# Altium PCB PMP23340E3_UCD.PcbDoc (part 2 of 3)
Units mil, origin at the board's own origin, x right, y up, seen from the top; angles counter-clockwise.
Board outline 2299.21 x 1157.48 mil, 14 copper layers (Top Layer, Layer 1, Layer 2, Layer 3, Layer 4, Layer 5, Layer 6, Layer 7, Layer 8, Layer 9, Layer 10, Layer 11, Layer 12, Bottom Layer), stack 130 mil thick; 242 components, 71 nets, 1021 pads, 321 vias.
Unrouted connection lines stored in the file: 1.
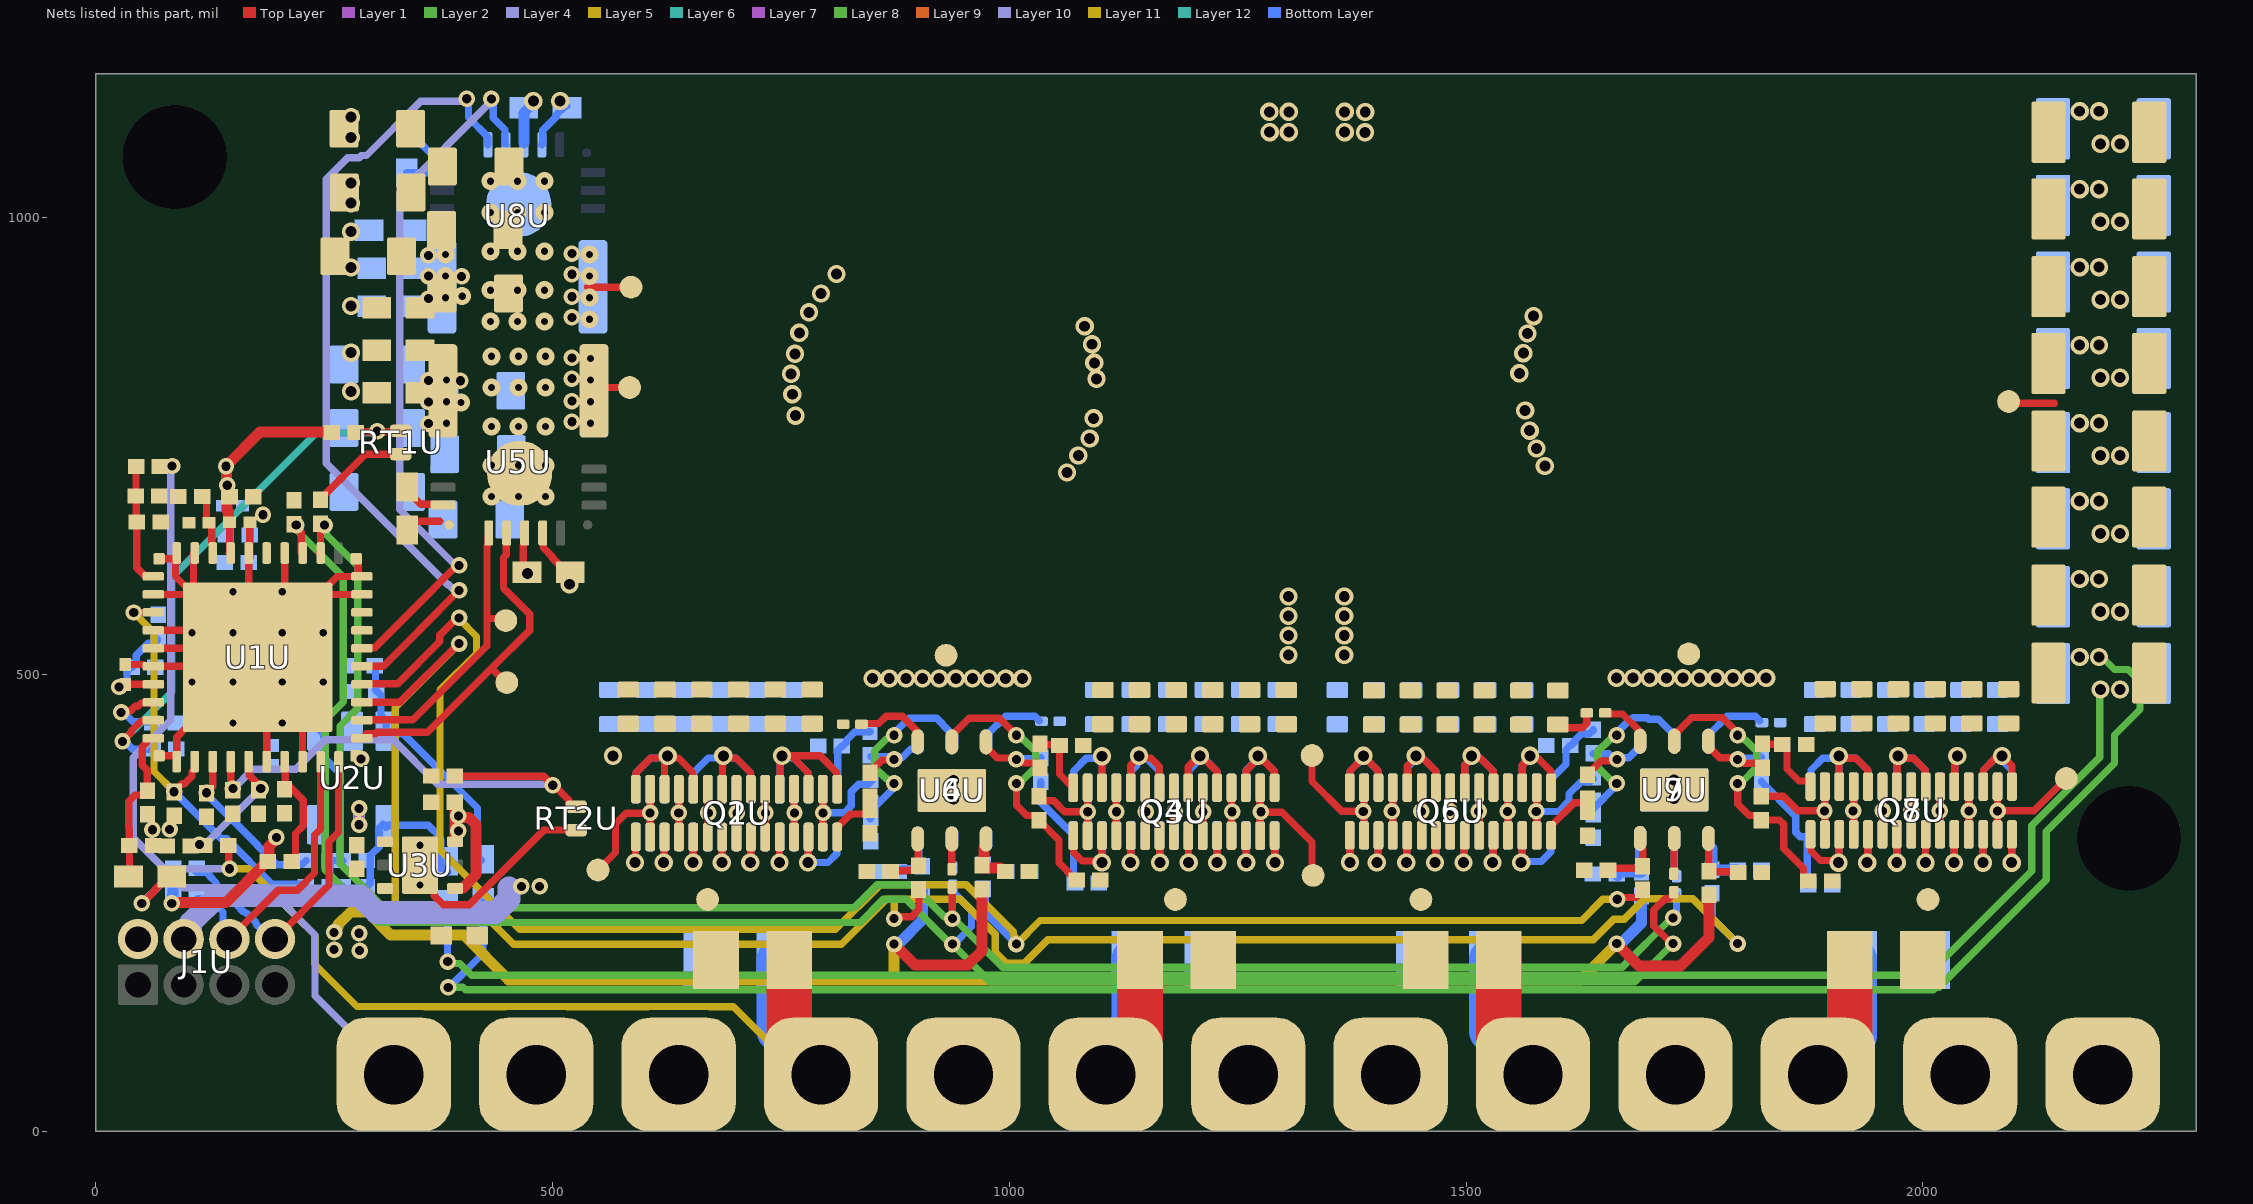
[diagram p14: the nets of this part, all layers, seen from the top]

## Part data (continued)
U2U: library part CMP-0032028-2, "CMOS Amplifier 1 Circuit Rail-to-Rail SOT-23-5", Digikey Part Number=296-TLV365DBVRCT-ND, Input Bias Current=0.000005uA, Input Offset Voltage=0.4mV, Manufacturer="Texas Instruments", Max Supply Voltage=5.5V, Min Supply Voltage=2.2V, Mouser Part Number=595-TLV365DBVR, Nominal Supply Current=4.6mA, Operating Temperature Range="-40°C to +125°C", Output Current Per Channel=85mA, Voltage Gain=120dB
U3U: library part CMP-0013427-7, "500mA LDO, DRV0006A (WSON-6)", Alternate Manufacturer="Texas Instruments"
U4U U6U U7U U9U: library part CMP-0013422-3, "UCD7xxx Low Side Power MOSFET Driver with Body Diode Conduction Sensing, DRS0006A (WSON-6)", Alternate Manufacturer="Texas Instruments"
U5U U8U: library part CMP-0097820-2, Manufacturer="Texas Instruments", Operating Temperature Range=to
ZZ1U: library part CMP-0003616-3
ZZ2U: library part CMP-0077236-1
ZZ3U: library part CMP-0077237-1
ZZ4U: library part CMP-0077238-1

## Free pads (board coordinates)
  round 114.17 hole 114.17 unplated: 2(86.41,1066.47) 2(2225.59,320.81)

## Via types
v1: diameter 20, hole 12, Top Layer to Bottom Layer, tented both sides, 153 vias
v2: diameter 18, hole 10, Top Layer to Bottom Layer, tented both sides, 108 vias
v3: diameter 19.68, hole 7.87, Top Layer to Bottom Layer, tented both sides, 58 vias
v4: diameter 19.68, hole 7.87, Top Layer to Bottom Layer, 2 vias

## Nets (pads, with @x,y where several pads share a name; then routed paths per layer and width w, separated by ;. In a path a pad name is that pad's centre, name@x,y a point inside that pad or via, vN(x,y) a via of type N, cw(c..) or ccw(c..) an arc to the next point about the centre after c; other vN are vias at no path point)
3_3V_A: C1U.2 C2U.1 R1U.1 U1U.37 | length 100.7
  Top Layer w8: C2U.1@30.58,489.81 C2U.1@31.76,490.99 ; C2U.1@31.93,489.14 U1U.37@61.73,489.14
  Bottom Layer w8: v2@29.38,489.73 34.16,494.51 34.16,503.61 38.43,507.88 C1U.2@39.22,507.88 39.88,507.88 44.15,512.14 44.15,521.11 57.46,534.42 64.08,534.42 67.13,537.47 R1U.1@67.13,538.64
  other v2: 25.59,486.22
3_3V_D: C3U.2 C4U.2 C5U.2 C6U.1 C7U.1 C17U.1 C25U.1 R1U.2 R2U.2 R3U.1 R4U.1 R9U.2 R10U.2 U1U.27 U2U.5 U3U.1 | length 641.3
  Top Layer w8: U1U.27@145.89,632.89 146.54,633.53 C6U.1@146.54,666.32
  Top Layer w12: v2@83.32,250.28 142.78,250.28 185.32,292.81 185.89,292.81 R2U.2@188.53,295.46 ; v2(143.86,707.01) 143.86,679.32 145.25,677.94 C6U.1@145.25,669.65 ; v2@145.51,706.02 143.19,708.34 143.19,727.2 v2(142.52,727.87) 179.88,765.24 258.18,765.24 R9U.2@259.96,763.46 ; R2U.2@189.65,295.46 189.65,311.93 197.67,319.94 v2(197.67,321.56) ; v2@288.7,354.31 v2@290.43,352.58
  Layer 1 w12: v2@287.23,333.89 288.33,334.99 v2(288.33,335.48) v2(288.33,353.31)
  Layer 2 w12: v2@288.33,334.82 v2(288.33,335.48) v2(288.33,353.31)
  Layer 4 w12: v2@288.12,335.32 v2(288.33,335.48) v2(288.33,353.31)
  Layer 5 w12: v2(288.33,353.31) 288.33,335.64 v2@288.47,335.5
  Layer 6 w12: v2(288.33,353.31) 288.33,337.95 v2@289.72,336.56
  Layer 7 w12: v2@288.12,336.56 288.33,336.77 v2(288.33,353.31)
  Layer 8 w12: v2@287.58,336.38 288.33,337.13 v2(288.33,353.31)
  Layer 9 w12: v2@287.41,336.03 288.33,336.95 v2(288.33,353.31)
  Layer 10 w12: v2@287.94,334.61 288.33,334.99 v2(288.33,335.48) v2(288.33,353.31)
  Layer 11 w12: v2@288.33,335.71 v2(288.33,353.31)
  Layer 12 w12: v2@287.05,334.61 v2@288.33,335.88 ; v2@287.23,334.43 v2(288.33,335.48) v2@288.33,335.88 ; v2(288.33,353.31) v2@288.33,335.88
  Bottom Layer w12: v2@83.32,250.28 83.98,250.94 83.98,258.24 R3U.1@84.65,258.91 84.65,285.61 R4U.1@85.56,285.61 ; v2(288.33,353.31) v2(288.33,335.48) 288.33,335.19 v2@289.13,334.38
  other v2: 83.14,249.4
5V: C24U.1 C44U.2 C94U.2 J1U.2 L1U.1 L2U.1 L3U.1 L4U.1 U3U.4 U3U.6 U5U.14 U8U.14 | length 2261.3
  Top Layer w8: U5U.14@468.61,657.45 468.61,642.01 467.81,641.21 467.81,615.21 v1(472.77,610.25)
  Top Layer w12: C24U.1@392.99,360.1 393.21,359.88 393.21,344.89 v2@393.44,344.66 ; v2@393.06,325.22 393.06,316.99 393.16,316.9 U3U.6@393.21,316.9 ; U3U.6@393.28,316.9 U3U.6@393.21,316.9 ; U3U.4@396.14,265.81 398.65,265.81 399.22,266.39 401.78,266.39 416.14,280.74 416.14,335.7 408.33,343.52 394.58,343.52 v2@393.44,344.66 ; v2(873.92,204.75) 896.77,181.9 899.17,181.9 ; 899.17,181.75 954.97,181.75 ; 954.97,182.3 970.05,197.38 L2U.1@970.05,265.17 ; v2(1664.88,205.38) 1689.35,180.91 1734.6,180.91 1765.81,212.12 L4U.1@1765.81,258.78 1765.81,259.15 L4U.1@1764.48,260.49 ; U3U.6@393.21,316.9 393.12,316.99 393.12,328.11 392.95,328.28 393.19,328.52 393.19,344.42 v2@393.44,344.66
  Layer 1 w12: J1U.2@46.09,206.08 J1U.2@46.09,211.13
  Layer 11 w12: v2(260.93,217.57) 260.93,219.2 265.18,223.44 265.18,226.21 278.65,239.68 297.71,239.68 322.8,214.59 402.95,214.59 451.79,165.75 1619.05,165.75 ; 872.73,166.53 873.92,167.72 v2(873.92,204.75) ; 1619.05,165.67 1625.18,165.67 v2(1664.88,205.38)
  Bottom Layer w12: U8U.14@468.5,1081.69 468.5,1114.8 479.51,1125.8 C94U.2@479.51,1126.45 ; v2(873.92,204.75) 875.07,205.89 879.57,205.89 904.71,231.03 L1U.1@904.71,263.99 904.71,265 L1U.1@905.56,265.85 ; v2(1664.88,205.38) 1666.03,206.52 1670.53,206.52 1691.8,227.79 1691.8,257.17 L3U.1@1690.96,258
  other v1: 479,1127.46
  other v2: 260.93,198.84 396.86,328.77 396.86,345.15
ADDR0: C13U.1 U1U.38 | length 74.3
  Top Layer w8: v2@29.23,459.03 30.55,460.35 38.25,460.35 42.98,465.08 45.87,465.08 49.56,468.76 61.05,468.76 U1U.38@61.73,469.45
  Bottom Layer w8: v2@29.02,458.25 30.65,458.25 40.74,448.16 60.54,448.16 C13U.1@61.79,446.91
  other v2: 27.76,458.44
AGND: C1U.1 C2U.2 C3U.1 C4U.1 C5U.1 C6U.2 C7U.2 C8U.1 C9U.2 C10U.1 C11U.2 C12U.2 C13U.2 C14U.1 C15U.1 C17U.2 C18U.1 C19U.1 C20U.1 C21U.1 C22U.1 C23U.1 C24U.2 C25U.2 NT1U.2 R14U.1 R15U.1 R16U.1 R17U.1 RT1U.2 RT2U.2 U1U.1 U1U.6 U1U.8 U1U.19 U1U.20 U1U.24 U1U.26 U1U.29 U1U.30 U1U.32 U1U.34 U1U.35 U1U.36 U1U.41 U1U.A1 U1U.A2 U1U.A3 U1U.A4 U2U.2 U3U.3 U3U.7@354.9,291.31 | length 1190
  Top Layer w8: C2U.2@32.22,510.82 52.25,510.82 54.25,508.82 98.22,508.82 103.93,503.11 U1U.41@103.93,492.65 ; U1U.35@61.73,528.51 98.22,528.51 105.1,535.39 U1U.41@105.1,544.48 ; U1U.34@61.73,548.19 102.56,548.19 U1U.41@104.16,546.59 ; U1U.32@61.73,587.56 U1U.41@107.01,587.56 ; U1U.A1@69.29,410.83 86.22,410.83 U1U.1@86.66,410.39 ; U1U.A4@69.29,626.57 85.14,626.57 U1U.30@85.66,626.05 ; U1U.30@87.33,626.05 87.33,607.25 U1U.41@107.01,587.56 ; U1U.1@88.58,404.53 88.58,431.34 98.25,441.01 142.81,441.01 U1U.41@149.19,447.39 ; U1U.29@107.01,632.84 107.01,593.46 U1U.41@112.37,588.1 ; U1U.41@110.96,583.41 110.96,583.61 U1U.41@107.01,587.56 ; U1U.41@125.03,585.99 123.46,587.56 U1U.41@107.01,587.56 ; U1U.41@147.55,590.68 161.61,590.68 167.32,596.39 U1U.26@167.32,632.87 ; C6U.2@168.58,666.32 168.58,627.08 U1U.26@168.63,627.03 ; U1U.6@187.01,404.53 187.01,441.01 192.22,446.22 U1U.41@202.43,446.22 ; U1U.41@206.29,589.14 206.69,589.55 U1U.24@206.69,632.87 ; U1U.41@224.84,456.13 226.38,454.59 U1U.8@226.38,404.53 ; U1U.41@235.02,586.7 235.89,587.56 U1U.19@290.08,587.56 ; U1U.41@240.89,589.04 246.28,589.04 264.49,607.25 U1U.20@290.08,607.25 ; C11U.2@243.39,692.81 246.94,692.81 295.23,741.09 RT1U.2@333.68,741.09 ; U1U.A3@283.97,627.04 284.58,627.04 U1U.A3@285.04,626.57 287.34,624.28 287.34,608.01 288.06,607.28 U1U.20@291.34,607.28 ; U3U.7@353.56,270.38 364.02,270.38 370.58,263.81 370.58,257.82 380.6,247.81 408.66,247.81 490.45,329.59 RT2U.2@525.89,329.59
  other v2: 288.77,197.66 288.18,216.68 61.94,329.92 80.81,330.34 290.35,407.48 183.07,674.8
  other v3: 150.2,446.85 204.13,446.85 105.32,491.73 150.2,491.73 204.13,491.73 249.02,491.73 105.32,545.67 150.2,545.67 204.13,545.67 249.02,545.67 150.2,590.55 204.13,590.55
  other v4: 354.9,269.65 354.9,312.96
BP18: C8U.2 C9U.1 U1U.28 | length 65.4
  Top Layer w8: C8U.2@116.32,694.72 116.93,694.72 121.2,690.45 121.2,668.14 121.81,667.54 C9U.1@123.58,667.54 ; C9U.1@124.16,665.84 124.61,665.84 126.91,663.54 126.91,643.49 128.08,642.31 U1U.28@128.08,633.86
DCT1A: C12U.1 R22U.1 R45U.1 U1U.23 | length 2168.3
  Top Layer w8: C12U.1@216.95,664.58 216.95,663.79 224.79,655.95 224.79,633.27 U1U.23@224.88,633.18 ; v2@1727.16,205.36 1724.89,205.36 1705.55,224.7 1705.55,242.1 1717.85,254.4 1722.01,254.4 1727.45,259.84 R45U.1@1727.45,261.64
  Layer 2 w8: v2@939.38,203.05 979.1,163.33 1684.5,163.33 v2(1726.55,205.38)
  Layer 8 w8: v2(219.44,663.44) 219.44,660.73 223.63,656.54 223.63,653.93 270.88,606.68 270.88,469.75 251.33,450.2 251.33,286 308.86,228.47 836.7,228.47 862.01,253.77 886.98,253.77 890.87,249.88 933.84,206.91 v2@933.84,202.66
  Bottom Layer w8: v2(937.68,204.75) 939.35,204.75 958.68,224.07 958.68,241.47 939.16,260.98 939.16,268.18 R22U.1@938.52,268.82 ; v2@1723.45,205.67 v2@1728.51,205.67
DCT1B: C11U.1 R31U.1 R36U.1 U1U.22 | length 2034.9
  Top Layer w8: U1U.22@244.28,632.8 245.9,634.42 C11U.1@245.9,664.99 ; R31U.1@937.66,267.45 937.47,267.25 937.47,232.98 v2(937.68,232.77)
  Layer 2 w8: v2(937.68,232.77) 939.35,232.77 992.8,179.33 1670.8,179.33 v2@1724.24,232.77
  Layer 8 w8: v2(250.49,663.44) 252.4,661.53 252.4,653.1 286.88,618.62 286.88,463.13 267.33,443.57 267.33,292.63 315.49,244.47 441.84,244.47 ; 442.98,244.47 830.08,244.47 855.38,269.77 893.61,269.77 928.69,234.68 935.76,234.68 v2(937.68,232.77)
  Bottom Layer w8: v2@1726.8,233.13 1726.8,236.36 1730.4,239.96 R36U.1@1730.4,259.07
  other v2: 1726.55,233.4
GND: C26U.1 C27U.1 C28U.1 C29U.1 C30U.1 C31U.1 C32U.1 C33U.1 C34U.1 C35U.1 C36U.1 C37U.1 C38U.2 C39U.2 C40U.2 C41U.2 C42U.2 C43U.1 C44U.1 C45U.1 C46U.2 C48U.1 C49U.2 C50U.1 C51U.1 C52U.1 C53U.1 C54U.1 C55U.1 C56U.1 C57U.1 C58U.1 C59U.1 C60U.1 C61U.1 C62U.1 C63U.1 C64U.1 C65U.1 C66U.1 C67U.1 C68U.1 C69U.1 C70U.1 C71U.1 C72U.1 C73U.1 C74U.2 C75U.2 C76U.2 C77U.2 C78U.2 C79U.2 C80U.2 C82U.1 C85U.2 C88U.1 C90U.1 C91U.2 C94U.1 C95U.1 C96U.2 C99U.1 C100U.1 C101U.1 C102U.1 C103U.1 C104U.1 C105U.1 C106U.1 C107U.1 C108U.1 C109U.1 C110U.1 C114U.1 C115U.1 C116U.1 C117U.1 C118U.1 C119U.1 C120U.1 C121U.1 C122U.1 C123U.1 C124U.1 C125U.1 C128U.2 C131U.2 C132U.2 C133U.2 C134U.2 C135U.1 Gnd1U.1 Gnd2U.1 Gnd3U.1 Gnd4U.1 Gnd5U.1 Gnd6U.1 J1U.4 NT1U.1 Q1U.2 Q1U.5 Q1U.6 Q1U.9 Q1U.10 Q1U.13 Q1U.14 Q1U.17 Q1U.18 Q1U.21 Q1U.22 Q1U.25 Q1U.26 Q1U.29 Q1U.30 Q2U.2 Q2U.5 Q2U.6 Q2U.9 Q2U.10 Q2U.13 Q2U.14 Q2U.17 Q2U.18 Q2U.21 Q2U.22 Q2U.25 Q2U.26 Q2U.29 Q2U.30 Q3U.2 Q3U.5 Q3U.6 Q3U.9 Q3U.10 Q3U.13 Q3U.14 Q3U.17 Q3U.18 Q3U.21 Q3U.22 Q3U.25 Q3U.26 Q3U.29 Q3U.30 Q4U.2 Q4U.5 Q4U.6 Q4U.9 Q4U.10 Q4U.13 Q4U.14 Q4U.17 Q4U.18 Q4U.21 Q4U.22 Q4U.25 Q4U.26 Q4U.29 Q4U.30 Q5U.2 Q5U.5 Q5U.6 Q5U.9 Q5U.10 Q5U.13 Q5U.14 Q5U.17 Q5U.18 Q5U.21 Q5U.22 Q5U.25 Q5U.26 Q5U.29 Q5U.30 Q6U.2 Q6U.5 Q6U.6 Q6U.9 Q6U.10 Q6U.13 Q6U.14 Q6U.17 Q6U.18 Q6U.21 Q6U.22 Q6U.25 Q6U.26 Q6U.29 Q6U.30 Q7U.2 Q7U.5 Q7U.6 Q7U.9 Q7U.10 Q7U.13 Q7U.14 Q7U.17 Q7U.18 Q7U.21 Q7U.22 Q7U.25 Q7U.26 Q7U.29 Q7U.30 Q8U.2 Q8U.5 Q8U.6 Q8U.9 Q8U.10 Q8U.13 Q8U.14 Q8U.17 Q8U.18 Q8U.21 Q8U.22 Q8U.25 Q8U.26 Q8U.29 Q8U.30 R21U.1 R23U.1 R30U.1 R32U.1 R35U.1 R39U.1 R44U.1 R46U.1 TP10U.1 TP11U.1 TP12U.1 TP13U.1 U4U.7@937.3,373.03 U5U.6 U5U.15 U6U.7@937.01,373.03 U7U.7@1727.87,373.66 U8U.6 U8U.15 U9U.7@1727.87,373.66 | length 5072.4
  Top Layer w8: U5U.15@489.22,654.82 490.14,653.9 490.14,638.49 499.79,628.84 499.79,627.62 C44U.1@516.87,610.53 ; v1(518.55,598.71) 519.15,599.31 C44U.1@519.15,612 ; v1@589.22,295.12 590.71,296.61 590.71,321.64 Q1U.29@591.14,322.06 ; Q1U.30@591.14,374.43 591.57,374.86 591.57,392.64 607.46,408.53 623.31,408.53 625.71,410.93 625.71,407.23 622.63,404.15 Q1U.26@622.63,374.43 ; v1@620.95,293.31 622.2,294.56 622.2,321.63 Q1U.25@622.63,322.06 ; v1@625.03,413.2 629.7,408.53 637.81,408.53 653.7,392.64 653.7,374.86 Q1U.22@654.13,374.43 ; v1@653.13,295.35 654.05,296.26 654.05,321.98 Q1U.21@654.13,322.06 ; v1@683.27,294.44 685.48,296.64 685.48,321.92 Q1U.17@685.63,322.06 ; Q1U.18@685.63,374.43 686.06,374.86 v1@686.06,410.25 ; v1@687.58,410.25 689.3,408.53 700.8,408.53 716.69,392.64 716.69,374.86 Q1U.14@717.12,374.43 ; v1@716.36,295.58 716.83,296.04 716.83,321.77 Q1U.13@717.12,322.06 ; v1@747.41,292.63 748.5,293.71 748.5,321.94 Q1U.9@748.62,322.06 ; Q1U.10@748.62,374.43 749.05,374.86 v1@749.05,406.22 ; v1@750.36,412.06 751.6,410.83 792.99,410.83 811.18,392.64 811.18,374.86 Q1U.2@811.61,374.43 ; 763.79,408.53 779.68,392.64 779.68,374.86 Q1U.6@780.11,374.43 ; v1@778.91,293.76 779.81,294.66 779.81,321.76 Q1U.5@780.11,322.06 ; Q3U.2@1069.89,323.46 1070.32,323.03 1070.32,305.25 1079.74,295.83 1099.79,295.83 v1@1101.18,294.44 ; v1@1100.5,295.58 1101.32,296.39 1101.32,323.39 Q3U.6@1101.39,323.46 ; Q3U.5@1101.39,375.82 v1@1101.38,410.68 ; v1@1129.28,295.12 1132.75,298.59 1132.75,323.32 Q3U.10@1132.88,323.46 ; Q3U.9@1132.88,375.82 1132.88,400.6 1141.12,408.84 1141.43,408.53 1154.67,408.53 1163.95,399.26 1163.95,376.26 Q3U.13@1164.38,375.82 ; Q3U.14@1164.38,323.46 1164.65,323.19 1164.65,293.75 v1@1164.86,293.54 ; Q3U.18@1195.87,323.46 1196.08,323.25 1196.08,295.18 v1@1196.36,294.9 ; Q3U.17@1195.87,375.82 1195.87,398.88 v1@1207.47,410.48 ; v1@1207.24,410.7 1210.27,410.7 1226.94,394.04 1226.94,376.26 Q3U.21@1227.37,375.82 ; Q3U.22@1227.37,323.46 1227.43,323.4 1227.43,295.1 v1@1227.64,294.9 ; Q3U.26@1258.87,323.46 1259.1,323.22 1259.1,295.84 v1@1259.37,295.58 ; Q3U.25@1258.87,375.82 1259.3,376.26 1259.3,394.9 v1@1273.01,408.62 ; v1@1271.15,410.48 1273.49,410.48 1289.93,394.04 1289.93,376.26 Q3U.29@1290.36,375.82 ; v1@1273.87,410.48 v1@1273.87,410.93 ; Q3U.30@1290.36,323.46 1290.53,323.29 1290.53,295.69 v1@1291.55,294.67 ; v1@1371.55,296.03 1372.8,297.28 1372.8,323.55 Q5U.29@1372.56,323.78 ; Q5U.30@1372.56,376.14 1372.99,376.58 1372.99,394.36 v1@1386.51,407.87 ; v1@1387.87,412.29 1387.87,410.46 1403.62,394.7 1403.62,376.58 Q5U.26@1404.05,376.14 ; v1@1400.78,293.31 1403.62,296.15 1403.62,323.35 Q5U.25@1404.05,323.78 ; v1@1431.61,294.44 1435.12,297.96 1435.12,323.35 Q5U.21@1435.55,323.78 ; Q5U.22@1435.55,376.14 1435.55,399.69 v1@1445.2,409.34 ; v1@1443.84,410.7 v1@1445.2,409.34 ; v1@1466.28,293.08 1466.61,293.42 1466.61,323.35 Q5U.17@1467.05,323.78 ; Q5U.18@1467.05,376.14 1466.61,376.58 1466.61,394.36 1452.41,408.57 1445.98,408.57 v1@1445.2,409.34 ; v1@1496.2,294.67 1498.11,296.58 1498.11,323.35 Q5U.13@1498.54,323.78 ; Q5U.14@1498.54,376.14 1498.54,400.63 v1@1505.49,407.58 ; v1@1507.3,409.57 1508.31,408.57 1515.4,408.57 1529.61,394.36 1529.61,376.58 Q5U.10@1530.04,376.14 ; v1@1528.6,293.08 1529.61,294.09 1529.61,323.35 Q5U.9@1530.04,323.78 ; v1@1561.24,296.26 1561.1,296.39 1561.1,323.35 Q5U.5@1561.54,323.78 ; Q5U.6@1561.54,376.14 1561.54,400.58 v1@1570.08,409.12 ; v1@1570.76,410.48 1572.67,408.57 1578.39,408.57 1592.6,394.36 1592.6,376.58 Q5U.2@1593.03,376.14 ; C67U.1@1600.8,444.14 1603.34,441.6 1627.51,441.6 1632.19,446.29 R46U.1@1632.19,457.87 ; Q7U.2@1877.01,324.89 1877.45,324.46 1877.45,306.67 1887.87,296.25 1907.54,296.25 v1@1908.21,295.58 ; v1@1906.63,409.57 1907.89,408.31 1926.73,408.31 1939.57,395.47 1939.57,377.68 Q7U.9@1940.01,377.25 ; v1@1907.2,296.6 1908.11,297.51 1908.11,324.49 Q7U.6@1908.51,324.89 ; v1@1908.27,407.93 1908.27,377.49 Q7U.5@1908.51,377.25 ; v1@1935.86,294.22 1939.57,297.93 1939.57,324.46 Q7U.10@1940.01,324.89 ; v1@1971.22,410.48 v1@1971.93,409.76 ; Q7U.14@1971.5,324.89 1971.45,324.83 1971.45,294.67 v1@1972.35,293.76 ; Q7U.13@1971.5,377.25 1971.93,377.68 v1@1971.93,409.76 ; Q7U.18@2003,324.89 2002.88,324.77 2002.88,296.33 v1@2004.76,294.44 ; Q7U.17@2003,377.25 2002.57,377.68 2002.57,395.47 1989.72,408.31 1973.38,408.31 v1@1971.93,409.76 ; Q7U.22@2034.49,324.89 2034.23,324.62 2034.23,295.12 v1@2035.81,293.54 ; Q7U.21@2034.49,377.25 2034.93,377.68 2034.93,404.61 2035.81,405.5 v1@2035.81,412.97 ; Q7U.26@2065.99,324.89 2065.9,324.79 2065.9,293.36 v1@2066.63,292.63 ; Q7U.25@2065.99,377.25 2066.42,377.68 2066.42,395.47 2079.27,408.31 v1@2084.21,408.31 ; v1@2086.57,411.61 2086.57,411.29 2097.49,400.38 Q7U.29@2097.49,377.25 ; v1@2097,293.99 2097.33,294.32 2097.33,324.73 Q7U.30@2097.49,324.89
  Layer 4 w25: J1U.4@96.2,210.27 96.2,215.44 103.65,222.89 103.65,227.89 133.43,257.67 288.91,257.67 307.27,239.31 437.55,239.31 452.2,253.96 452.2,266.14
  Bottom Layer w8: U8U.15@488.19,1079.72 489.11,1080.65 489.11,1095.58 504,1110.46 504,1112.27 513.84,1122.1 C94U.1@515.64,1122.1 ; v1@589.22,296.71 590.71,298.2 590.71,321.64 Q2U.30@591.14,322.06 ; Q2U.29@591.14,374.43 591.57,374.86 591.57,392.64 607.46,408.53 623.76,408.53 v1@624.57,409.34 ; v1@620.72,293.54 622.2,295.02 622.2,321.63 Q2U.26@622.63,322.06 ; Q2U.25@622.63,374.43 622.63,404.15 624.57,406.09 v1@624.57,409.34 ; v1@624.57,411.16 v1@624.57,409.34 ; v1@626.61,411.38 v1@624.57,409.34 ; v1@652,294.67 654.05,296.72 654.05,321.98 Q2U.22@654.13,322.06 ; Q2U.21@654.13,374.43 654.56,374.86 654.56,392.64 670.45,408.53 682.91,408.53 v1@684.4,410.02 ; v1@684.86,294.44 685.48,295.06 685.48,321.92 Q2U.18@685.63,322.06 ; Q2U.17@685.63,374.43 686.06,374.86 v1@686.06,410.02 ; v1@689.3,408.53 700.8,408.53 716.69,392.64 716.69,374.86 Q2U.13@717.12,374.43 ; Q2U.14@717.12,322.06 716.83,321.77 716.83,296.92 v1@717.49,296.26 ; v1@746.95,292.86 748.5,294.4 748.5,321.94 Q2U.10@748.62,322.06 ; Q2U.9@748.62,374.43 749.05,374.86 749.05,407.82 v1@750.35,409.12 ; v1@752.03,408.53 763.79,408.53 779.68,392.64 779.68,374.86 Q2U.5@780.11,374.43 ; v1@777.55,293.08 v1@778.8,294.33 ; v1@778.46,294.67 v1@778.8,294.33 ; Q2U.6@780.11,322.06 779.81,321.76 779.81,295.34 v1@778.8,294.33 ; Q2U.2@811.61,322.06 811.18,321.63 811.18,303.85 801.5,294.17 v1(779.5,294.17) 778.95,294.17 v1@778.8,294.33 ; Q4U.2@1069.98,376.14 1070.42,376.57 1070.42,394.35 1084.2,408.14 1100.43,408.14 v1@1101.18,408.89 ; v1@1098.23,407.99 1098.33,407.99 1101.43,404.89 1101.43,376.19 Q4U.6@1101.48,376.14 ; v1@1100.05,296.48 1101.36,297.8 1101.36,323.66 Q4U.5@1101.48,323.78 ; v1@1132.23,294.67 1132.79,295.23 1132.79,323.59 Q4U.9@1132.98,323.78 ; Q4U.10@1132.98,376.14 1133.41,376.57 1133.41,394.35 1139.75,400.7 1139.75,406.22 v1@1142.09,408.55 ; v1@1139.48,411.16 v1@1142.09,408.55 ; v1@1143.33,409.8 v1@1142.09,408.55 ; Q4U.13@1164.47,323.78 1164.7,323.55 1164.7,297.78 v1@1167.58,294.9 ; Q4U.14@1164.47,376.14 1164.04,376.57 1164.04,394.35 1149.86,408.53 v1@1142.11,408.53 ; v1@1195.01,293.08 1196.13,294.21 1196.13,323.62 Q4U.17@1195.97,323.78 ; Q4U.18@1195.97,376.14 1196.4,376.57 1196.4,395.19 1207.92,406.71 v1@1207.92,409.8 ; v1@1209.76,411.63 1227.03,394.35 1227.03,376.57 Q4U.22@1227.46,376.14 ; Q4U.21@1227.46,323.78 1227.48,296.64 v1@1229,295.12 ; v1@1258.24,294.9 1259.15,295.81 1259.15,323.59 Q4U.25@1258.96,323.78 ; Q4U.26@1258.96,376.14 1259.39,376.57 1259.39,394.99 1272.51,408.11 v1@1272.51,412.06 ; v1@1273.87,407.76 1276.62,407.76 1290.02,394.35 1290.02,376.57 Q4U.30@1290.46,376.14 ; Q4U.29@1290.46,323.78 1290.58,323.65 1290.58,294.05 v1@1291.32,293.31 ; Q6U.30@1372.56,323.78 1372.8,323.55 1372.8,294.11 v1@1373.14,293.76 ; Q6U.29@1372.56,376.14 1372.99,376.58 1372.99,394.36 1387.42,408.78 v1@1387.42,412.97 ; v1@1388.3,410.02 1403.62,394.7 1403.62,376.58 Q6U.25@1404.05,376.14 ; v1@1401.92,293.54 1403.62,295.24 1403.62,323.35 Q6U.26@1404.05,323.78 ; v1@1435.01,295.12 1435.12,295.23 1435.12,323.35 Q6U.22@1435.55,323.78 ; Q6U.21@1435.55,376.14 1435.98,376.58 1435.98,398.64 1442.71,405.37 v1@1442.71,410.7 ; v1@1444.96,408.57 1452.41,408.57 1466.61,394.36 1466.61,376.58 Q6U.17@1467.05,376.14 ; Q6U.18@1467.05,323.78 1466.61,323.35 1466.61,294.34 v1@1467.19,293.76 ; v1@1498.47,293.08 1498.11,293.44 1498.11,323.35 Q6U.14@1498.54,323.78 ; Q6U.13@1498.54,376.14 1498.54,400.58 v1@1507.98,410.02 ; v1@1507.98,408.57 1515.4,408.57 1529.61,394.36 1529.61,376.58 Q6U.9@1530.04,376.14 ; v1@1529.97,296.03 1529.61,296.39 1529.61,323.35 Q6U.10@1530.04,323.78 ; v1@1560.11,292.86 1562.55,295.3 1582.33,295.3 1592.6,305.57 1592.6,323.35 Q6U.2@1593.03,323.78 ; v1@1561.1,294.98 1561.1,323.35 Q6U.6@1561.54,323.78 ; Q6U.5@1561.54,376.14 1561.54,400.63 1570.31,409.41 v1@1570.31,410.02 ; Q8U.2@1877.01,377.25 1877.45,377.68 1877.45,395.47 1890.29,408.31 1906.96,408.31 v1@1907.54,408.89 ; Q8U.5@1908.51,324.89 1908.11,324.49 1908.11,297.49 v1@1908.67,296.94 ; Q8U.6@1908.51,377.25 1908.27,377.49 1908.27,408.31 1926.73,408.31 1939.57,395.47 1939.57,377.68 Q8U.10@1940.01,377.25 ; v1@1939.94,295.58 1939.57,295.95 1939.57,324.46 Q8U.9@1940.01,324.89 ; Q8U.13@1971.5,324.89 1971.45,324.83 1971.45,294.44 v1@1972.35,293.54 ; Q8U.14@1971.5,377.25 1971.93,377.68 1971.93,408.48 v1@1972.58,409.12 ; v1@1977.01,408.31 1989.72,408.31 2002.57,395.47 2002.57,377.68 Q8U.18@2003,377.25 ; Q8U.17@2003,324.89 2002.88,324.77 2002.88,296.1 v1@2004.99,293.99 ; v1@2034.45,293.31 2034.23,293.53 2034.23,324.62 Q8U.21@2034.49,324.89 ; Q8U.22@2034.49,377.25 2034.93,377.68 2034.93,404.61 2038.53,408.21 v1@2038.53,411.61 ; v1@2065.27,293.31 2065.9,293.94 2065.9,324.79 Q8U.25@2065.99,324.89 ; Q8U.26@2065.99,377.25 2066.42,377.68 2066.42,395.47 2079.27,408.31 2083.5,408.31 v1@2085.67,410.48 ; v1@2088.99,408.51 2088.99,403.53 2097.05,395.47 2097.05,377.68 Q8U.30@2097.49,377.25 ; v1@2097.23,293.08 2097.33,293.18 2097.33,324.73 Q8U.29@2097.49,324.89
  other v1: 590.28,294.17 621.65,294.17 653.96,294.17 685.33,294.17 716.53,294.17 748.37,294.17 1101.25,294.17 1132.61,294.17 1164.93,294.17 1196.29,294.17 1227.5,294.17 1259.34,294.17 1290.7,294.17 1373.03,294.29 1402.24,294.21 1434.55,294.21 1465.92,294.21 1497.12,294.21 1528.96,294.21 1560.33,294.21 1907.71,293.96 1939.07,293.96 1971.39,293.96 2002.75,293.96 2033.96,293.96 2065.8,293.96 2097.17,293.96 938.68,363.34 1727.55,363.97 938.68,384.03 1727.55,384.66 566.06,410.83 626.06,410.83 686.89,410.83 751.06,410.83 1101.38,410.43 1142.05,410.83 1208.79,410.83 1271.98,410.83 1387.46,410.86 1444.96,410.86 1505.79,410.86 1569.96,410.86 1908.03,410.61 1973,410.61 2037.68,410.61 2086.7,410.61 279.32,809.88 279.32,852.18 279.32,903.25 279.32,945.55 279.32,984.65 279.32,1015.9 279.32,1038.12 279.32,1087.73 279.32,1109.95 508.28,1127.73
  other v2: 465.84,268.03 485.86,268.03
  other v3: 433.11,694.66 462.64,694.66 492.17,694.66 433.11,728.91 462.64,728.91 492.17,728.91 433.11,771.43 462.64,771.43 492.17,771.43 433.11,813.95 462.64,813.95 492.17,813.95 433.11,848.21 462.64,848.21 492.17,848.21 432.09,886.34 461.61,886.34 491.14,886.34 432.09,920.59 461.61,920.59 491.14,920.59 432.09,963.11 461.61,963.11 491.14,963.11 432.09,1005.63 461.61,1005.63 491.14,1005.63 432.09,1039.88 461.61,1039.88 491.14,1039.88
IOCP: C14U.2 R12U.2 U1U.3 | length 180.5
  Top Layer w8: C14U.2@120.91,371.25 121.5,371.25 127.95,377.71 U1U.3@127.95,404.53
  Bottom Layer w8: v2@120.73,369.33 176.67,313.39 176.67,312.87 188.97,300.56 189.49,300.56 198.35,291.7 220.59,291.7 220.99,292.11 226.06,292.11 R12U.2@230.33,296.37
  other v2: 121.17,370.45
IOSNS: C15U.2 R18U.2 U1U.2 U1U.33 | length 472.9
  Top Layer w8: v2(41.61,567.77) 41.66,567.82 63.4,567.82 U1U.33@63.72,568.15 ; U1U.2@108.39,406.91 108.39,396.48 105.37,393.46 105.37,388.65 97.2,380.48 94.8,380.48 90.64,376.33 90.11,376.33 C15U.2@85.8,372.02 ; C15U.2@85.8,372.02 v2(85.8,371.56) C15U.2@85.8,372.02
  Layer 5 w8: v2(41.61,567.77) 63.7,545.67 63.7,393.66 v2(85.8,371.56) v2@86.54,370.81
  Bottom Layer w8: v2@83.85,372.07 85.29,372.07 v2(85.8,371.56) 137.26,320.1 143.38,320.1 192.92,270.56 R18U.2@230.01,270.56
NetC16U_1: C16U.1 R5U.1 R12U.1 R18U.1 U2U.1 | length 212.5
  Bottom Layer w8: U2U.1@243.11,440.94 249.49,434.56 249.49,409.26 267.33,391.42 C16U.1@267.33,296.6 ; U2U.1@245.29,446.41 U2U.1@245.36,446.48 ; R18U.1@255.99,267.88 256.07,267.8 269.92,267.8 R5U.1@270.86,266.85 ; R18U.1@256.31,268.2 R12U.1@256.31,296.37 270.23,296.37 C16U.1@270.61,296 ; R5U.1@270.39,267.8 R5U.1@270.47,267.72
NetC16U_2: C16U.2 R5U.2 R11U.2 U2U.4 | length 181.4
  Bottom Layer w8: R5U.2@296.46,267.72 300.31,271.57 C16U.2@300.31,302.32 ; C16U.2@301.12,302.34 310.31,311.53 310.31,331.52 U2U.4@314.69,335.9 ; U2U.4@317.91,332.68 320.04,334.8 363.94,334.8 376.74,322.01 376.74,319.19 377.53,318.4 R11U.2@377.53,287.91 ; R11U.2@380.61,288.2 R11U.2@385.24,283.56
NetC23U_2: C23U.2 R13U.2 R17U.2 U2U.3 | length 264.5
  Bottom Layer w8: R17U.2@305.4,509.5 306.27,508.63 306.27,483.13 C23U.2@307.8,481.59 ; C23U.2@307.13,481.45 307.92,481.45 312.18,477.18 312.18,455.35 U2U.3@318.73,448.8 ; U2U.3@318.1,437.15 320.57,434.68 337.04,434.68 417.86,353.85 417.86,300.68 R13U.2@422.08,296.47 ; U2U.3@318.12,443.31 U2U.3@318.12,447.6
NetC38U_1: C38U.1 L1U.2 U4U.3 | length 55.6
  Bottom Layer w8: C38U.1@879.13,284.45 881.9,287.21 L1U.2@903.15,287.21 ; U4U.3@899.89,319.88 901,318.78 901,294.91 L1U.2@904.54,291.37
NetC43U_2: C43U.2 R19U.2 U4U.1 | length 56.1
  Bottom Layer w8: R19U.2@971.46,291.54 973.59,293.67 973.59,320.62 U4U.1@976.1,323.12 ; R19U.2@975.72,287.99 993.31,287.99 C43U.2@996.85,284.45
NetC45U_2: C45U.2 Q1U.1 R24U.1 | length 65.4
  Top Layer w8: Q1U.1@811.61,322.06 811.61,332.38 826.03,346.79 828.32,346.79 ; 828.32,347.16 C45U.2@843.19,347.16 ; C45U.2@846.47,349.2 847.46,350.18 C45U.2@847.46,352.09 R24U.1@847.46,366.31
NetC46U_1: C46U.1 Q2U.1 R25U.2 | length 78
  Bottom Layer w8: Q2U.1@812.07,384.21 812.07,385.12 812.31,385.36 812.31,417.24 816.58,421.51 C46U.1@816.71,421.51 ; C46U.1@816.92,420.93 821.77,425.78 821.77,427.92 831.13,437.29 R25U.2@847.6,437.29
NetC47U_1: C47U.1 U5U.10 | length 47.1
  Top Layer w8: C47U.1@343.65,703.22 343.65,698.49 355.89,686.25 379.04,686.25 U5U.10@379.96,685.33 U5U.10@379.56,684.93
NetC47U_2: C47U.2 U5U.11 | length 40.1
  Top Layer w8: C47U.2@340.29,659.18 340.29,659.51 348.58,667.8 376.67,667.8
NetC48U_2: C48U.2 Q3U.1 R26U.1 | length 70.4
  Top Layer w8: R26U.1@1033.45,424 1034.33,423.12 C48U.2@1052.31,423.12 ; C48U.2@1054.92,422.24 1054.92,390.94 Q3U.1@1068.95,376.91
NetC49U_1: C49U.1 Q4U.1 R27U.2 | length 124.3
  Bottom Layer w8: R27U.2@1034.45,382.68 1034.45,359.95 Q4U.1@1068.84,325.55 ; Q4U.1@1069.98,323.78 1070.19,323.57 1070.19,274.88 C49U.1@1072.96,272.11
NetC74U_1: C74U.1 L2U.2 U6U.3 | length 60.4
  Top Layer w12: U6U.3@974.59,320.1 974.59,312.69 972.32,310.42 972.32,293.28 L2U.2@970.05,291.01 970.05,290.35 972.32,288.08 990.56,288.08 995,283.64 C74U.1@995,282.56
NetC82U_2: C82U.2 R28U.2 U6U.1 | length 61.4
  Top Layer w8: C82U.2@871.2,285.07 886.81,285.07 887.35,285.62 896.32,285.62 900.1,289.4 900.1,319.39 U6U.1@899.61,319.88
NetC85U_1: C85U.1 L3U.2 U7U.3 | length 64.8
  Bottom Layer w12: C85U.1@1665.81,279.95 1665.81,281.4 1667.87,283.46 L3U.2@1691.8,283.46 ; U7U.3@1690.47,320.51 1690.81,320.17 L3U.2@1690.81,284.16
NetC88U_2: C88U.2 R33U.2 U7U.1 | length 65.8
  Bottom Layer w12: U7U.1@1765.27,320.51 1765.27,313.14 1769.16,309.26 R33U.2@1769.16,286.33 ; R33U.2@1769,286.21 1769.29,285.92 1796.32,285.92 C88U.2@1798.12,284.12
NetC90U_2: C90U.2 Q5U.1 R37U.1 | length 72.9
  Top Layer w8: Q5U.1@1593.03,323.78 1593.03,334.1 1618.42,359.49 R37U.1@1627.64,359.49 ; R37U.1@1632.87,363.98 C90U.2@1632.87,349.61 1632.87,347.25 C90U.2@1633.39,346.73
NetC91U_1: C91U.1 Q6U.1 R38U.2 | length 76.4
  Bottom Layer w8: Q6U.1@1593.49,385.92 1609.34,401.77 1609.34,417.77 1613.61,422.04 C91U.1@1613.87,422.04 ; C91U.1@1615.57,422.96 1618.92,426.31 1618.92,427.65 1625.96,434.68 1634.93,434.68 1639.2,438.95 R38U.2@1639.2,439.61
NetC95U_2: C95U.2 Q7U.1 R40U.1 | length 87.3
  Top Layer w8: R40U.1@1824.36,424 1824.75,423.62 C95U.2@1845.78,423.62 ; C95U.2@1846.26,423.23 1846.92,423.23 1851.19,418.96 1851.19,396.57 1864.39,383.37 1875.7,383.37 1877.01,382.06 Q7U.1@1877.01,377.25
NetC96U_1: C96U.1 Q8U.1 R41U.2 | length 138.5
  Bottom Layer w8: R41U.2@1823.34,383.31 1823.34,382.52 1860.95,344.91 1860.95,327.07 1865.64,322.38 1872.14,322.38 Q8U.1@1872.54,321.98 ; C96U.1@1872.94,269.22 1873.48,269.75 Q8U.1@1873.48,321.98
NetC98U_1: C98U.1 U8U.10 | length 45.1
  Bottom Layer w8: C98U.1@340.55,1049.21 U8U.10@378.94,1049.21 384.36,1049.21 U8U.10@385.29,1050.14
NetC98U_2: C98U.2 U8U.11 | length 61
  Bottom Layer w8: C98U.2@340.55,1096.46 340.55,1092.52 348.36,1084.71 352.3,1084.71 368.01,1069 U8U.11@387.86,1069
NetC128U_1: C128U.1 L4U.2 U9U.3 | length 68.2
  Top Layer w8: U9U.3@1763.7,318.15 1765.54,316.3 L4U.2@1765.54,285.19 ; L4U.2@1764.07,285.19 1765.23,284.02 1797.06,284.02 C128U.1@1797.8,283.29
NetC135U_2: C135U.2 R42U.2 U9U.1 | length 71.9
  Top Layer w8: C135U.2@1655.32,285.6 1657.58,287.86 R42U.2@1691.93,287.86 ; U9U.1@1689.63,322.96 1689.63,312.9 1693.21,309.32 R42U.2@1693.21,290.11
NetR20U_1: R20U.1 R21U.2 U4U.5 | length 211.1
  Layer 2 w8: v2@873.92,434.33 871.22,434.33 866.14,429.26 865.22,429.26 852.92,416.96 852.92,397.99 865.18,385.74 866.26,385.74 870.69,381.31 v2@874.63,381.31
  Bottom Layer w8: R21U.2@847.69,341.64 848.29,342.24 R21U.2@848.29,343.35 R20U.1@848.29,358.7 ; R20U.1@852.45,354.55 872.01,374.11 872.01,379.08 v2@873.92,380.99 ; v2@874.81,436.69 890.08,451.96 920.39,451.96 934.41,437.95 934.41,437.52 937.3,434.63 U4U.5@937.3,428.17
  other v2: 873.92,380.79 873.92,433.35
NetR22U_2: R22U.2 U4U.2 | length 32.4
  Bottom Layer w6: U4U.2@937.3,319.88 937.64,319.53 937.64,289.43 R22U.2@938.93,288.14
NetR23U_2: R23U.2 U4U.6 | length 75.8
  Bottom Layer w8: U4U.6@974.7,426.18 974.7,433.07 995.98,454.35 1027.66,454.35 1032.61,449.4 R23U.2@1032.71,449.4
NetR29U_1: R29U.1 R30U.2 U6U.5 | length 294.3
  Top Layer w8: U6U.5@938.04,432.58 938.04,434.17 955.83,451.96 989.14,451.96 v2(1007.75,433.35) ; v2@1005.89,378.21 1007.75,376.35 1007.75,356.91 1019.18,345.49 1028.15,345.49 1032.41,341.22 R29U.1@1032.41,340.56 1054.35,318.63 1054.35,293.69 1070.6,277.43 R30U.2@1072.05,277.43
  Layer 2 w8: v2(1007.75,433.35) 1010.46,433.35 1015.78,428.03 1016.45,428.03 1028.75,415.73 1028.75,398.34 1013.12,382.7 1012.37,382.7 1009.52,379.84 v2@1009.52,378.81
  other v2: 1007.75,380.79
NetR31U_2: R31U.2 U6U.2 | length 32.7
  Top Layer w8: R31U.2@937.26,286.84 937.14,286.97 937.14,318 U6U.2@938.22,319.08
NetR32U_2: R32U.2 U6U.6 | length 80.5
  Top Layer w8: R32U.2@838.16,445.56 838.85,446.25 857.13,446.25 865.22,454.35 882.62,454.35 898.5,438.47 898.5,432.09 U6U.6@901.05,429.54
NetR34U_1: R34U.1 R35U.2 U7U.5 | length 199.1
  Layer 2 w8: v2(1664.88,433.35) 1662.17,433.35 1656.86,428.03 1656.57,428.03 1644.27,415.73 1644.27,398.34 1659.91,382.7 1664.36,382.7 v2@1667.42,379.63
  Bottom Layer w8: R34U.1@1638.08,353.59 1639.63,353.59 v2@1662.97,376.92 ; v2@1665.39,432.08 1665.39,436.57 1679.77,450.94 1681,450.94 1682.65,452.59 1698.29,452.59 1699.94,450.94 1710.63,450.94 1727.87,433.7 U7U.5@1727.87,426.81
  other v2: 1664.88,380.79
NetR36U_2: R36U.2 U7U.2 | length 41.8
  Bottom Layer w8: U7U.2@1727.87,320.51 1727.87,280.48 R36U.2@1729.15,279.21
NetR39U_2: R39U.2 U7U.6 | length 73.5
  Bottom Layer w8: U7U.6@1765.27,426.81 1765.27,433.7 1785.92,454.35 1816.37,454.35 R39U.2@1821.31,449.4
NetR43U_1: R43U.1 R44U.2 U9U.5 | length 322.1
  Top Layer w8: U9U.5@1727.03,432.86 1746.96,452.79 1780.54,452.79 1797.52,435.81 v2@1797.52,433.1 ; v2(1797.27,380.79) 1797.27,358.09 1809.87,345.49 1819.23,345.49 R43U.1@1823.28,341.44 ; R43U.1@1823.11,339.77 R43U.1@1823.11,340.56 1843.11,340.56 1847.8,335.87 1847.8,309.38 1869.61,287.57 1869.61,278.12 R44U.2@1874.93,272.8
  Layer 2 w8: v2@1794.97,380.82 1796.84,382.7 1802.64,382.7 1818.27,398.34 1818.27,415.73 1805.97,428.03 1805.29,428.03 1799.98,433.35 v2(1797.27,433.35)
NetR45U_2: R45U.2 U9U.2 | length 44.3
  Top Layer w8: R45U.2@1727.45,281.66 1727.66,281.87 1727.66,324.7 U9U.2@1728.51,325.56
NetR46U_2: R46U.2 U9U.6 | length 59.1
  Top Layer w8: R46U.2@1652.22,457.87 1653.34,456.74 1671.19,456.74 1689.36,438.56 1689.36,427.82 U9U.6@1691.63,425.55
PMBUS_SCL: J1U.6 R3U.2 U1U.9 | length 315.3
  Top Layer w8: J1U.6@141.72,210.49 146.42,210.49 199.78,263.85 220.56,263.85 239.35,282.64 239.35,323.96 246.06,330.68 U1U.9@246.06,404.53
  Bottom Layer w8: R3U.2@111.56,254.79 124.54,254.79 139.3,240.03 139.3,222.83 J1U.6@147.8,214.33
PMBUS_SDA: J1U.8 R4U.2 U1U.10 | length 343.6
  Top Layer w8: J1U.8@195.81,211.35 197.28,211.35 255.35,269.42 255.35,316.95 265.75,327.35 U1U.10@265.75,404.53
  Bottom Layer w8: R4U.2@108.95,285.26 110.6,283.61 120.78,283.61 125.47,278.93 125.47,278.37 131.69,272.15 131.69,270.27 137.1,264.85 137.87,264.85 154.66,248.06 154.66,247.29 161.05,240.91 cw(c146.2,210.27) 176.84,225.12 ; 176.84,225.12 191.69,210.27 J1U.8@196.2,210.27
PWM0A: TP1U.1 U1U.11 U5U.13 | length 376.8
  Top Layer w8: U1U.11@291.34,430.12 296.3,435.08 306.13,435.08 307.58,436.53 363.08,436.53 433.17,506.62 ; U5U.13@449.35,656.29 449.35,631.07 446.29,628.01 446.29,594.49 451.5,589.29 474.96,565.83 474.96,548.4 433.17,506.62 ; TP1U.1@449.91,491.04 448.75,491.04 433.17,506.62
PWM0B: TP2U.1 U1U.12 U5U.12 | length 318.9
  Top Layer w8: U1U.12@291.34,449.8 292.06,450.53 347.28,450.53 428.29,531.54 428.29,561.11 ; U5U.12@430.69,654.48 429.24,653.03 429.24,642.01 428.29,641.06 428.29,561.11 ; TP2U.1@451.36,558.57 448.82,561.11 428.29,561.11
PWM1A: R28U.1 R33U.1 U1U.13 | length 2194.5
  Top Layer w8: U1U.13@291.34,469.49 332.73,469.49 396.98,533.74 v2(397.69,533.74) ; v2(873.92,232.77) 875.84,234.68 893.07,234.68 901.2,242.81 R28U.1@901.2,266.41 ; R28U.1@898.64,261.83 R28U.1@900.76,259.71
  Layer 11 w8: v2(397.69,533.74) 327.79,463.84 327.79,245.07 336.61,236.25 425.84,236.25 457.34,204.75 816.2,204.75 865.22,253.77 874.43,253.77 ; v2(873.92,232.77) 873.92,253.27 874.43,253.77 ; v2@1797.55,204.65 1797.55,205.1 1748.25,254.4 1695.71,254.4 1673.21,231.9 1661.71,231.9 1639.21,209.41 1042.11,209.41 1016.45,183.75 996.78,183.75 984.46,196.07 984.46,215.69 946.38,253.77 874.43,253.77
  Bottom Layer w8: R33U.1@1768.54,260.72 1769.43,259.83 1769.43,233.22 v2(1797.27,205.38)
PWM1B: R19U.1 R42U.1 U1U.14 | length 1922
  Top Layer w8: U1U.14@291.34,489.17 292.06,489.9 330.51,489.9 376.69,536.07 376.69,542.81 395.76,561.89 v2@396.49,561.89 ; v2(1665.43,253.82) 1667.35,255.73 1685.56,255.73 R42U.1@1688.91,259.07 ; R42U.1@1688.94,259.07 R42U.1@1693.91,264.04
  Layer 11 w8: v2@397.51,562.49 397.51,560.79 416.69,541.61 416.69,522.59 376.69,482.59 376.74,482.55 376.74,307.98 463.97,220.75 809.57,220.75 858.6,269.77 953,269.77 1004.62,218.16 1004.62,214.43 1005.84,213.21 1005.84,209.18 v2@1004.62,207.96 ; v2(1007.75,204.75) 1033.66,230.66 1626.53,230.66 1649.69,253.82 v2(1665.43,253.82)
  Bottom Layer w8: R19U.1@970.56,265.42 973.49,262.49 973.49,249.29 974.68,248.1 974.68,237.82 v2(1007.75,204.75)
  other v2: 397.69,561.89
PWM2A: U1U.15 U8U.12 | length 901.4
  Top Layer w8: U1U.15@291.34,508.86 314.85,508.86 354.85,548.86 ; 354.68,549.03 v2(397.69,592.03)
  Layer 4 w8: v2@395.16,592.03 392.46,592.03 386.24,598.26 385.14,598.26 252.21,731.19 252.21,1042.12 275.81,1065.73 288.43,1065.73 290.64,1067.93 296.25,1067.93 355.65,1127.34 v2@408.08,1127.34
  Bottom Layer w8: v2@407.22,1128.45 408.01,1127.66 408.01,1109.71 429.13,1088.58 U8U.12@429.13,1079.72
  other v2: 406.09,1130.19
PWM2B: U1U.16 U8U.13 | length 771.1
  Top Layer w8: U1U.16@291.34,528.54 292.06,529.27 305.49,529.27 344.21,567.99 ; 344.08,568.12 394.96,619 v2@397.47,619
  Layer 4 w8: v2@393.84,619.26 332.58,680.51 332.58,1026.98 v2@431.78,1126.18
  Bottom Layer w8: v2@434.34,1127.8 434.98,1127.15 434.98,1109.07 447.9,1096.16 447.9,1080.65 U8U.13@448.82,1079.72
  other v2: 397.69,619.26 433.07,1129.92
PWM3A: U1U.17
PWM3B: U1U.18
PWROK: U1U.25
RESET: C10U.2 R2U.1 U1U.7 | length 124.7
  Top Layer w8: U1U.7@206.03,405.91 207.42,404.53 207.42,381.8 226.96,362.25 226.96,334.2 218.67,325.91 218.67,299.35 R2U.1@214.36,295.08
SR1A1: R24U.2 R25U.1 U4U.4 | length 96.6
  Top Layer w8: R24U.2@849.41,391.02 849.41,395.03 860.73,406.35 872.01,406.35 v2@873.92,408.26
  Bottom Layer w8: R25U.1@848.08,410.24 848.54,409.78 872.4,409.78 873.24,408.95 882.38,408.95 883.61,410.18 883.89,410.18 891.9,418.19 897.22,418.19 899.89,420.86 U4U.4@899.89,426.18
  other v2: 873.92,407.03
SR1B1: R26U.2 R27U.1 U6U.4 | length 99.3
  Top Layer w8: U6U.4@974.41,426.18 974.41,420.86 986.75,408.51 1007.89,408.51 v2@1008.84,407.56 ; v2@1010.46,407.03 1014.55,402.95 1030.73,402.95 R26U.2@1034.59,399.09
  Bottom Layer w8: v2@1008.41,407.37 1008.89,407.85 1033.64,407.85 R27U.1@1034.45,408.66
  other v2: 1007.75,407.03
SR2A1: R40U.2 R41U.1 U9U.4 | length 99.4
  Top Layer w8: U9U.4@1765.27,426.81 1765.27,421.48 1777.81,408.95 v2@1795.9,408.95 ; v2(1797.27,407.03) 1799.98,407.03 1804.09,402.92 1820.1,402.92 R40U.2@1824.2,398.83
  Bottom Layer w8: v2@1796.36,407.02 1797.51,408.16 1822.22,408.16 R41U.1@1823.34,409.29
SR2B1: R37U.2 R38U.1 U7U.4 | length 104.6
  Top Layer w8: R37U.2@1630.01,389.62 R37U.2@1631.75,389.62 ; R37U.2@1634.48,390.93 1634.48,392.35 1647.25,405.12 1663.36,405.12 v2(1665.27,407.03)
  Bottom Layer w8: R38U.1@1639.03,413.18 1656.42,413.18 1662.57,407.03 v2(1665.27,407.03) ; v2@1665.27,408.95 1677.93,408.95 1690.47,421.48 U7U.4@1690.47,426.81
TEMP_P: C21U.2 R9U.1 RT1U.1 U1U.39 | length 622.6
  Top Layer w8: v2(29.23,426.72) 39.18,436.67 39.18,438.65 49.61,449.08 61.18,449.08 U1U.39@61.68,449.59 ; R9U.1@284.43,764.83 285.35,765.76 333.16,765.76 RT1U.1@333.68,766.28
  Layer 6 w8: v2(29.23,426.72) 83.47,480.96 83.47,606.28 241.39,764.2 304.45,764.2 v2@307.32,767.08
  Bottom Layer w8: v2@29.02,428 30.66,428 40.47,418.19 C21U.2@62.1,418.19
  other v2: 307.93,766.12
TEMP_S: C22U.2 R10U.1 RT2U.1 U1U.4 | length 574.8
  Top Layer w8: U1U.4@147.64,404.53 147.64,377.34 v2(150.06,374.93) 149.91,374.78 C22U.2@149.91,373.33 ; R10U.1@392.99,388.64 490.46,388.64 499.7,379.41 500.93,379.41 518.08,362.26 518.08,358.07 521.81,354.34 RT2U.1@525.99,354.34
  Layer 4 w8: v2(150.06,374.93) 150.73,374.93 171.84,396.03 218.89,396.03 251.33,428.48 325.52,428.48 374.14,379.86 498.92,379.86 v2(500.15,378.63)
Vin: C26U.2 C27U.2 C28U.2 C29U.2 C30U.2 C31U.2 C32U.2 C33U.2 C34U.2 C35U.2 C36U.2 C37U.2 C75U.1 C76U.1 C77U.1 C78U.1 C79U.1 C80U.1 R8U.2 U5U.7 U8U.7 Vin1U.1 | length 434.9
  Top Layer w8: v2(50.27,249.4) 51.05,249.4 65.24,263.59 65.24,264.81 79.59,279.17 R8U.2@84.64,279.17
  Layer 10 w8: v2(50.27,249.4) 73.49,272.63 89.61,272.63 95.93,266.32 188.31,266.32 239.93,214.69 239.93,148.17 277.15,110.94 277.15,66.67 Vin1U.1@276.63,66.14
  other v2: 364.17,774.61 364.17,798.23 364.17,821.85 399.11,821.43 364.17,911.42 400.42,935.64 364.17,936.02 364.17,958.66
  other v3: 383.9,774.9 399.77,797.8 383.9,798.52 383.9,822.14 382.87,912.4 401.08,913.98 382.87,936.02 382.87,959.65
VINSNS: C20U.2 R8U.1 R16U.2 U1U.40 | length 177.6
  Top Layer w8: R8U.1@36.41,278.46 36.83,278.88 R16U.2@36.83,312.62 36.62,312.83 36.62,332.4 36.15,332.86 36.15,360.91 43.18,367.94 52.15,367.94 57.02,372.81 C20U.2@57.02,373.05 ; C20U.2@56.42,372.87 56.42,395.27 50.99,400.7 50.99,420.95 55.18,425.14 55.18,429.39 55.59,429.8 U1U.40@63.12,429.8
VOSNS1: C18U.2 R6U.1 R14U.2 U1U.31 | length 131.6
  Top Layer w8: R14U.2@43.64,695.23 44.27,694.6 44.27,667.12 C18U.2@44.1,666.95 ; R6U.1@44.23,727.74 43.93,727.45 43.93,697.07 R14U.2@45.27,695.73 ; C18U.2@44.9,666.63 44.9,616.6 54.07,607.44 U1U.31@61.32,607.44
VOSNS2: C19U.2 R7U.1 R15U.2 U1U.5 | length 153.5
  Top Layer w6: v2(180.54,375.03) 181.04,374.53 182.7,372.87 C19U.2@184.13,372.87
  Top Layer w8: R15U.2@103.91,312.39 104.03,312.5 121.54,312.5 R7U.1@121.92,312.89 ; U1U.5@167.32,404.53 168.05,403.8 168.05,389.74 182.11,375.68 C19U.2@182.11,374.71
  Layer 4 w8: v2(113.49,313.84) 115.4,315.75 121.25,315.75 149.43,343.93 179.27,373.76 v2@179.27,377.96
Vout: C39U.1 C40U.1 C41U.1 C42U.1 C50U.2 C51U.2 C52U.2 C53U.2 C54U.2 C55U.2 C56U.2 C57U.2 C58U.2 C59U.2 C60U.2 C61U.2 C62U.2 C63U.2 C64U.2 C65U.2 C66U.2 C67U.2 C68U.2 C69U.2 C70U.2 C71U.2 C72U.2 C73U.2 C99U.2 C100U.2 C101U.2 C102U.2 C103U.2 C104U.2 C105U.2 C106U.2 C107U.2 C108U.2 C109U.2 C110U.2 C114U.2 C115U.2 C116U.2 C117U.2 C118U.2 C119U.2 C120U.2 C121U.2 C122U.2 C123U.2 C124U.2 C125U.2 C131U.1 C132U.1 C133U.1 C134U.1 Q1U.3 Q1U.4 Q1U.7 Q1U.8 Q1U.11 Q1U.12 Q1U.15 Q1U.16 Q1U.19 Q1U.20 Q1U.23 Q1U.24 Q1U.27 Q1U.28 Q2U.3 Q2U.4 Q2U.7 Q2U.8 Q2U.11 Q2U.12 Q2U.15 Q2U.16 Q2U.19 Q2U.20 Q2U.23 Q2U.24 Q2U.27 Q2U.28 Q3U.3 Q3U.4 Q3U.7 Q3U.8 Q3U.11 Q3U.12 Q3U.15 Q3U.16 Q3U.19 Q3U.20 Q3U.23 Q3U.24 Q3U.27 Q3U.28 Q4U.3 Q4U.4 Q4U.7 Q4U.8 Q4U.11 Q4U.12 Q4U.15 Q4U.16 Q4U.19 Q4U.20 Q4U.23 Q4U.24 Q4U.27 Q4U.28 Q5U.3 Q5U.4 Q5U.7 Q5U.8 Q5U.11 Q5U.12 Q5U.15 Q5U.16 Q5U.19 Q5U.20 Q5U.23 Q5U.24 Q5U.27 Q5U.28 Q6U.3 Q6U.4 Q6U.7 Q6U.8 Q6U.11 Q6U.12 Q6U.15 Q6U.16 Q6U.19 Q6U.20 Q6U.23 Q6U.24 Q6U.27 Q6U.28 Q7U.3 Q7U.4 Q7U.7 Q7U.8 Q7U.11 Q7U.12 Q7U.15 Q7U.16 Q7U.19 Q7U.20 Q7U.23 Q7U.24 Q7U.27 Q7U.28 Q8U.3 Q8U.4 Q8U.7 Q8U.8 Q8U.11 Q8U.12 Q8U.15 Q8U.16 Q8U.19 Q8U.20 Q8U.23 Q8U.24 Q8U.27 Q8U.28 R6U.2 R7U.2 R20U.2 R29U.2 R34U.2 R43U.2 TP4U.1 TP5U.1 TP6U.1 TP7U.1 TP8U.1 TP9U.1 Vout1U.1 Vout2U.1 Vout3U.1 Vout4U.1 Vout5U.1 Vout6U.1 | length 6005.6
  Top Layer w8: R6U.2@72.25,728.17 72.47,727.95 83.29,727.95 v2(83.5,728.16) ; v2@144.39,290.43 145.67,291.71 145.67,311.82 R7U.2@144.87,312.62 ; TP8U.1@548.13,286.93 550.81,286.93 568.84,304.97 568.84,336.39 580.37,347.91 606.29,347.91 v2(606.77,348.4) ; Q1U.27@606.89,322.06 606.89,347.91 Q1U.28@606.89,374.43 ; Q1U.23@638.38,322.06 Q1U.24@638.38,374.43 ; Q1U.19@669.88,322.06 Q1U.20@669.88,374.43 ; Q1U.15@701.37,322.06 Q1U.16@701.37,374.43 ; Q1U.11@732.87,322.06 Q1U.12@732.87,374.43 ; Q1U.7@764.37,322.06 Q1U.8@764.37,374.43 ; Q1U.3@795.66,334.47 v2@795.66,347.84 ; v2@795.86,348.76 Q1U.4@795.86,374.43 ; v2(796.23,348.4) v2@796.78,347.84 ; R29U.2@1031.11,367.78 1031.11,367.18 1036.68,361.61 1048.53,361.61 1060.49,349.65 v2@1085.64,349.65 ; Q3U.4@1085.64,323.46 v2@1085.64,349.65 ; Q3U.3@1085.64,375.82 v2@1085.64,349.65 ; v2(1085.84,349.65) v2@1085.64,349.65 ; Q3U.8@1117.13,323.46 Q3U.7@1117.13,375.82 ; Q3U.12@1148.63,323.46 Q3U.11@1148.63,375.82 ; Q3U.16@1180.13,323.46 Q3U.15@1180.13,375.82 ; Q3U.20@1211.62,323.46 Q3U.19@1211.62,375.82 ; Q3U.24@1243.12,323.46 Q3U.23@1243.12,375.82 ; Q3U.28@1274.61,323.46 Q3U.27@1274.61,375.82 ; v2(1275.3,349.65) 1275.71,349.24 1298.42,349.24 1331.4,316.26 TP6U.1@1331.4,289.61 ; TP7U.1@1331.4,411.23 1331.4,382.83 1363.87,350.36 1387,350.36 v2(1387.36,350) ; Q5U.27@1388.31,333.56 1388.31,350.36 Q5U.28@1388.31,376.14 ; Q5U.23@1419.8,323.78 Q5U.24@1419.8,376.14 ; Q5U.19@1451.3,323.78 Q5U.20@1451.3,376.14 ; Q5U.15@1482.8,323.78 Q5U.16@1482.8,376.14 ; Q5U.11@1514.29,323.78 Q5U.12@1514.29,376.14 ; Q5U.7@1545.79,333.56 Q5U.8@1545.79,376.14 ; Q5U.3@1577.28,333.56 Q5U.4@1577.28,376.14 ; R43U.2@1823.11,366.54 1847.07,366.54 1862.94,350.67 1891.27,350.67 v2@1892.37,351.77 ; Q7U.4@1892.76,324.89 v2@1892.76,350.59 ; v2@1892.76,351.77 Q7U.3@1892.76,367.47 ; Q7U.8@1924.05,336.55 1924.26,336.75 Q7U.7@1924.26,377.25 ; Q7U.12@1955.75,334.67 Q7U.11@1955.75,377.25 ; Q7U.16@1987.25,334.67 Q7U.15@1987.25,377.25 ; Q7U.20@2018.75,334.67 Q7U.19@2018.75,377.25 ; Q7U.24@2050.24,334.67 Q7U.23@2050.24,377.25 ; Q7U.28@2081.74,334.67 Q7U.27@2081.74,377.25 ; v2(2081.76,350.59) 2081.85,350.67 2121.62,350.67 2154.86,383.9 TP5U.1@2154.86,384.97
  Top Layer w50: C132U.1@758.95,187.39 758.95,100.18 793.91,65.22 Vout4U.1@793.91,61.81 ; Vout3U.1@1105.65,61.81 1105.65,65.22 1143.09,102.66 C131U.1@1143.09,187.39 ; C133U.1@1535.72,187.39 1535.72,102.77 1573.27,65.22 Vout2U.1@1573.27,61.81 ; Vout1U.1@1885.02,61.81 1885.02,65.22 1919.87,100.07 C134U.1@1919.87,187.39
  Layer 4 w8: v2@81.65,726.27 82.22,725.71 82.22,450.01 40.94,408.73 40.94,321.22 74.84,287.32 v2(146.47,287.32)
  Layer 11 w8: v2(146.47,287.32) 167.31,287.32 220.28,234.34 239.93,214.69 239.93,182.39 285.91,136.41 357.59,136.41 cw(c357.59,93.11) 362.42,136.14 446.03,136.14 cw(c450.86,93.11) 450.86,136.41 513.46,136.41 cw(c513.46,93.11) 518.29,136.14 601.9,136.14 cw(c606.74,93.11) 606.74,136.41 669.33,136.41 cw(c669.33,93.11) 674.17,136.14 698.06,136.14 700.4,133.8 774.49,59.71 Vout4U.1@788.1,59.71
  Layer 12 w8: Vout4U.1@752.16,103.56 Vout4U.1@793.91,61.81
  Bottom Layer w8: Q2U.28@606.89,322.06 Q2U.27@606.89,374.43 ; Q2U.24@638.38,322.06 Q2U.23@638.38,374.43 ; Q2U.20@669.88,322.06 Q2U.19@669.88,374.43 ; Q2U.16@701.37,322.06 Q2U.15@701.37,374.43 ; Q2U.12@732.87,322.06 Q2U.11@732.87,374.43 ; Q2U.8@764.37,322.06 Q2U.7@764.37,374.43 ; Q2U.4@795.86,322.06 Q2U.3@795.86,374.43 ; v2(796.23,348.4) 796.48,348.65 818.05,348.65 818.2,348.8 819.51,348.8 826.92,356.21 826.92,371.63 835.05,379.76 845.55,379.76 R20U.2@849.31,383.52 ; Q4U.3@1085.73,333.56 v2@1085.73,349.65 ; Q4U.4@1085.73,376.14 v2@1085.73,349.65 ; v2@1087.62,351.03 1086.25,349.65 v2(1085.84,349.65) v2@1085.73,349.65 ; Q4U.7@1117.23,323.78 Q4U.8@1117.23,376.14 ; Q4U.11@1148.72,323.78 Q4U.12@1148.72,376.14 ; Q4U.15@1180.22,323.78 Q4U.16@1180.22,376.14 ; Q4U.19@1211.72,323.78 Q4U.20@1211.72,376.14 ; Q4U.23@1243.21,323.78 Q4U.24@1243.21,376.14 ; Q4U.27@1274.71,323.78 Q4U.28@1274.71,376.14 ; Q6U.28@1388.25,324.14 Q6U.27@1388.25,376.5 ; Q6U.24@1419.74,324.14 Q6U.23@1419.74,376.5 ; Q6U.20@1451.24,324.14 Q6U.19@1451.24,376.5 ; Q6U.16@1482.74,324.14 Q6U.15@1482.74,376.5 ; Q6U.12@1514.23,324.14 Q6U.11@1514.23,376.5 ; Q6U.8@1545.79,323.78 Q6U.7@1545.79,376.14 ; v2(1576.82,350) v2@1577.28,350 ; Q6U.4@1577.28,323.78 v2@1577.28,350 ; Q6U.3@1577.28,376.14 v2@1577.28,350 ; R34U.2@1639.02,385.94 1635.6,382.52 1625.96,382.52 1612.71,369.27 1612.71,361.62 1601.09,350 v2@1577.28,350 ; Q8U.3@1892.76,334.67 Q8U.4@1892.76,377.25 ; Q8U.7@1924.26,324.89 Q8U.8@1924.26,377.25 ; Q8U.11@1955.75,324.89 Q8U.12@1955.75,377.25 ; Q8U.15@1987.25,324.89 Q8U.16@1987.25,377.25 ; Q8U.19@2018.75,324.89 Q8U.20@2018.75,377.25 ; Q8U.23@2050.24,324.89 Q8U.24@2050.24,377.25 ; Q8U.27@2081.74,324.89 Q8U.28@2081.74,377.25
  Bottom Layer w50: C42U.1@748.49,187.39 748.49,110.64 793.91,65.22 Vout4U.1@793.91,61.81 ; Vout3U.1@1105.65,61.81 1136.87,93.03 C41U.1@1136.87,187.39 ; C40U.1@1528.25,187.39 1528.25,110.25 1573.27,65.22 Vout2U.1@1573.27,61.81 ; Vout1U.1@1885.02,61.81 1885.02,65.22 1924.62,104.82 C39U.1@1924.62,187.39
  other v1: 850.37,495.61 868.57,495.61 886.78,495.61 904.99,495.61 923.2,495.61 941.41,495.61 959.61,495.61 977.82,495.61 996.03,495.61 1014.24,495.61 1664.58,496.06 1682.78,496.06 1700.99,496.06 1719.2,496.06 1737.41,496.06 1755.62,496.06 1773.82,496.06 1792.03,496.06 1810.24,496.06 1828.45,496.06
  other v2: 638.14,348.4 670.45,348.4 701.82,348.4 733.02,348.4 764.86,348.4 1117.21,349.65 1149.52,349.65 1180.89,349.65 1212.09,349.65 1243.93,349.65 1418.72,350 1451.04,350 1482.4,350 1513.61,350 1545.45,350 1892.31,350.59 1923.67,350.59 1955.99,350.59 1987.35,350.59 2018.56,350.59 2050.4,350.59
Vsw1: C81U.2 C83U.2 C84U.2 C86U.2 C87U.2 C89U.2 C92U.2 C93U.2 C97U.2 C111U.2 C112U.2 C113U.2 C126U.2 C127U.2 C129U.2 C130U.2 R13U.1 TP3U.1 TP15U.1 U5U.5 | length 2320.9
  Top Layer w8: U5U.5@541.11,812.91 542.35,814.14 TP15U.1@584.4,814.14 ; TP3U.1@2093.86,798.81 2095.77,796.89 2143.71,796.89
  Layer 8 w8: v2(385.83,157.48) 401.81,157.48 404.62,154.67 2011.62,154.67 2014.43,157.48 2017.31,157.48 2135.17,275.33 2135.17,328.09 2209.66,402.59 2209.66,433.7 2237.66,461.7 2237.66,492.49 2224.78,505.38 2209.73,505.38 2196.12,518.99 v1(2192.88,518.99)
  Bottom Layer w8: v2@384.66,157.48 386.85,157.48 423.94,194.57 R13U.1@423.94,250.53
  other v1: 2171.6,518.99 2171.6,604.34 2192.88,604.34 2171.6,689.69 2192.88,689.69 2171.6,775.05 2192.88,775.05 2171.6,860.4 2192.88,860.4 2171.6,945.76 2192.88,945.76 2171.6,1031.11 2192.88,1031.11 2171.6,1116.46 2192.88,1116.46
  other v2: 521.13,776.51 521.13,799.15 521.13,823.76 521.13,846.4
  other v3: 541.38,774.9 541.38,798.52 541.38,822.14 541.38,845.77
Vsw2: C81U.1 C83U.1 C84U.1 C86U.1 C87U.1 C89U.1 C92U.1 C93U.1 C97U.1 C111U.1 C112U.1 C113U.1 C126U.1 C127U.1 C129U.1 C130U.1 R11U.1 TP14U.1 U8U.5 | length 2128.2
  Top Layer w8: 538.61,923.89 TP14U.1@585.95,923.89
  Layer 8 w8: v2(385.23,185.57) 387.14,183.65 398.27,183.65 411.25,170.67 2005,170.67 2119.17,284.84 2119.17,334.72 2193.66,409.22 2193.66,480.28 v1@2191.94,482
  Bottom Layer w8: R11U.1@384.88,248.29 385.05,248.12 385.05,184.12 v2@385.39,183.79
  other v1: 2194.38,483.38 2215.66,483.38 1305.47,521.14 1366.6,521.14 1305.47,542.49 1366.6,542.49 1305.47,563.85 1366.6,563.85 2194.38,568.73 2215.66,568.73 1305.47,585.2 1366.6,585.2 2194.38,654.09 2215.66,654.09 1063.08,721 1586.13,728.07 1075.54,739.65 2194.38,739.44 2215.66,739.44 1577.15,747.42 1087.91,758.12 1569.55,766.76 1092.38,780.3 765.95,783.23 1564.71,788.87 762.45,806.7 1095.44,823.56 2194.38,824.79 2215.66,824.79 760.92,829.09 1558.23,829.64 1093.06,841.04 765.41,850.95 1562.61,851.64 1090.53,861.42 770.19,873.86 1567.1,873.12 1082.51,881.13 1573.81,892.13 780.68,896.33 2194.38,910.15 2215.66,910.15 793.96,917 810.88,938.42 2194.38,995.5 2215.66,995.5 2194.38,1080.86 2215.66,1080.86 1285.03,1093.56 1305.96,1093.56 1367.09,1093.56 1389.21,1093.38 1284.62,1115.8 1305.96,1115.8 1367.09,1115.8 1389.62,1115.62
  other v2: 521.13,890.75 521.13,913.38 521.13,937.99 521.13,960.63
  other v3: 540.35,888.78 540.35,912.4 540.35,936.02 540.35,959.65
pads on no net: J1U.1 J1U.3 J1U.5 J1U.7 Q1U. Q2U. Q3U. Q4U. Q5U. Q6U. Q7U. Q8U. RT1U.1S RT1U.2S RT2U.1S RT2U.2S U1U.21 U3U.2 U3U.5 U3U.7@354.9,273.59 U3U.7@354.9,309.02 U4U.7@937.3,373.03 U5U.1 U5U.2 U5U.3 U5U.4 U5U.8 U5U.9 U5U.16 U6U.7@937.01,373.03 U7U.7@1727.87,373.66 U8U.1 U8U.2 U8U.3 U8U.4 U8U.8 U8U.9 U8U.16 U9U.7@1727.87,373.66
